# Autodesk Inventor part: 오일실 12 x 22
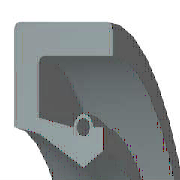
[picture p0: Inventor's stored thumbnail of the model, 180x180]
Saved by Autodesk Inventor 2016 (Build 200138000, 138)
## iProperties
IsCustomPart: 0
Created: 2015-10
Part Number: 오일실 12 x 22
Material: Rubber
Description: 오일-실
Document SubType Name: Modeling
Standard: KS B 2804
Designer: mdu
Standards Organization: KS
Language: ko-KR
Size Designation: S - 12 22 7
Categories: <MemberInstance><Categories><Category DisplayName="샤프트 부품" InternalName="7f7aeb1f-a693-4053-b835-cee3144e0d98" Mnemonic="SHFT"><Category DisplayName="실링" Intern
Density: 0.93 g/cm^3
Appearance: Rubber - Black - Version 1.1
Author: mdu
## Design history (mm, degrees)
revolve "본체" stored, may be unused: angle "d17" = 90 deg
revolve "스프링1" stored, may be unused: angle "d18" = 90 deg
body "Solid1"
sketch "스케치1"
  geometry: L1 (0, 11)-(7, 11); L2 (7, 11)-(7, 9.75); L3 (7, 9.75)-(1.75, 9.75); L4 (0, 11)-(0, 8.1); L5 (0, 8.1)-(1.75, 7.75); L6 (1.75, 7.75)-(4.9, 6); L7 (4.9, 6)-(0, 6); L8 (6.3, 6.875)-(6.3, 8.1); L9 (0, 0)-(9.586, 0) reference; L10 (4.9, 6)-(6.3, 6.875); L11 (0, 18)-(0, -3) reference; L12 (-1.917, 0)-(11.503, 0) reference; L13 (4.2, 8.1)-(1.75, 8.59); L14 (1.75, 8.59)-(1.75, 9.75); L15 (6.3, 8.1)-(5.6, 8.1); C1 r 0.455 at (4.9, 8.1); A1 r 0.7 centre (4.9, 8.1) between (5.6, 8.1) and (4.2, 8.1)
  constraints: 26 end point, 5 horizontal alignment, 4 perpendicular, 2 centre point, 2 collinear, 2 horizontal, 2 parallel, 2 point on circle, 2 point on line, 2 vertical alignment, 1 coincident
  dimensions: "d0" = 22 diameter of L1 L9 (= SD2); "d1" = 13.75 diameter of L8.start L9 (= ABDM); "d2" = 1.25 distance of L1.end L2.end (computed from SD); "d3" = 0.91 diameter of C1 (= SPDI); "d4" = 1.4 diameter of A1 (= SPDA); "d5" = 12 diameter of L6.end L9 (= NND); "d6" = 15.5 diameter of L5.end L9 (= TKDM); "d7" = 16.2 diameter of L4.end L9 (= HLDM); "d8" = 4.9 distance from line of C1.centre L4 (= SPDST); "d9" = 6.3 distance between parallel lines of L8 L4 (= SDI); "d10" = 7 distance between parallel lines of L2 L4 (= SWDT); "d12" = 1.75 distance between parallel lines of L14 L4 (= SD)
fillet "모깎기1" dims "d11" = 0.3 (= RR)
other parameters: "SD2" = 22 [user parameter; used in 1 equation term], "SWDT" = 7 [user parameter; used in 1 equation term], "RR" = 0.3 [user parameter; used in 1 equation term], "SD" = 1.75 [user parameter; used in 2 equation terms], "NND" = 12 [user parameter; used in 1 equation term], "SPDA" = 1.4 [user parameter; used in 1 equation term], "SPDI" = 0.91 [user parameter; used in 1 equation term], "TKDM" = 15.5 [user parameter; used in 1 equation term], "HLDM" = 16.2 [user parameter; used in 1 equation term], "ABDM" = 13.75 [user parameter; used in 1 equation term], "SDI" = 6.3 [user parameter; used in 1 equation term], "SPDST" = 4.9 [user parameter; used in 1 equation term], "d13" = 0, "d14" = 0, "d15" = 0, "LAB" = 0.35 [user parameter]
